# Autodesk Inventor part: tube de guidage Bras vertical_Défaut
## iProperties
Shininess: 64.0
Length Units: 11269
Angle Units: 11279
Time Units: 11290
Mass Units: 11283
Length Display Precision: 3
Angle Display Precision: 2
Compacted: True
Part Number: tube de guidage Bras vertical_Défaut
Document SubType Name: Modeling
Created: 2006-11
Material: Par défaut
Designer: profs_sti
Density: 0.0
Volumn: 0.0
Area: 0.0
PropertySet Name: Model Information
Control State: 0
Master: False
Checked Out: False
Author: profs_sti
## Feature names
1. Base1
